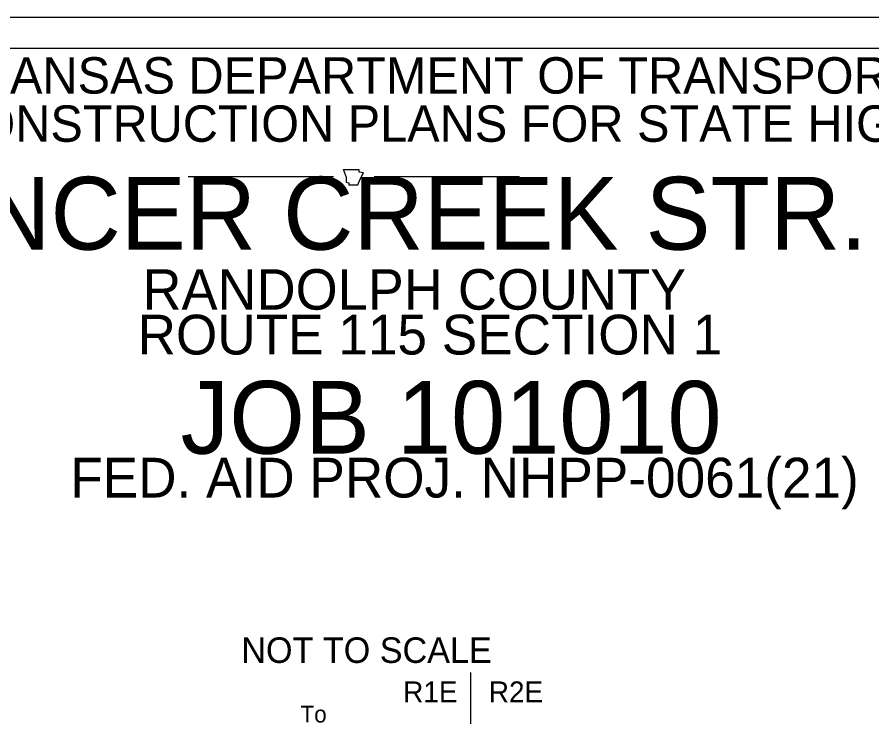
# Model space of a CAD drawing. Extents: x 1369885 to 1370219, y 379980 to 380218.
# Drawn here: x 1370011.5 to 1370119.1, y 380128.7 to 380217.9 of the extents above; entities that cross this region are included whole.
import ezdxf

# ---------------------------------------------------------------- set-up
doc = ezdxf.new("R2010")
doc.units = 0
for name, color, linetype in [('Default', 7, 'Continuous'), ('Level 2', 7, 'Continuous'), ('Level 24', 7, 'Continuous'), ('R_Draft', 7, 'Continuous'), ('R_No Plot', 7, 'Continuous'), ('STAMP_PE_FOSTER-SIGNATURE', 7, 'Continuous')]:
    doc.layers.add(name, color=color, linetype=linetype)

msp = doc.modelspace()

# ---------------------------------------------------------------- linework, layer by layer
at = {"layer": 'Default'}
for p, q in [((1370033.03, 380197.86), (1370051.34, 380197.86)), ((1370056.43, 380197.86), (1370074.74, 380197.86))]:
    msp.add_line(p, q, dxfattribs=at)
msp.add_lwpolyline([(1370052.53, 380198.79), (1370052.92, 380197.78), (1370052.92, 380197.15), (1370053.24, 380197.08), (1370053.24, 380196.84), (1370054.39, 380196.84), (1370054.63, 380197.47), (1370055.1, 380198.32), (1370054.55, 380198.4), (1370054.55, 380198.71), (1370052.61, 380198.71)], dxfattribs=at)
at = {"layer": 'R_Draft'}
msp.add_line((1370068.6, 380129.05), (1370068.6, 380135.48), dxfattribs=at)
at = {"layer": 'R_No Plot'}
msp.add_line((1369885.41, 380217.92), (1370218.74, 380217.92), dxfattribs=at)
msp.add_lwpolyline([(1369885.4, 380217.92), (1370218.74, 380217.92), (1370218.74, 380004.58), (1369885.4, 380004.58)], close=True, dxfattribs=at)
at = {"layer": 'STAMP_PE_FOSTER-SIGNATURE'}
for p, q in [((1369897.81, 380214.03), (1370213.99, 380214.03)), ((1370050.33, 380213.77), (1370050.33, 380213.77)), ((1370050.33, 380213.77), (1370050.33, 380213.77)), ((1370051.38, 380213.32), (1370051.38, 380213.32)), ((1370051.38, 380213.32), (1370051.38, 380213.32))]:
    msp.add_line(p, q, dxfattribs=at)

# ---------------------------------------------------------------- texts
at = {"layer": 'Default'}
for s, p in [(' R1E', (1370059.12, 380131.74)), ('R2E', (1370070.87, 380131.74))]:
    msp.add_text(s, height=2.63, dxfattribs=at).set_placement(p)
at = {"layer": 'Level 2'}
for s, height, p in [('ARKANSAS DEPARTMENT OF TRANSPORTATION', 4.5784, (1369998.04, 380208.3)), ('CONSTRUCTION PLANS FOR STATE HIGHWAY', 4.5784, (1370002.1, 380202.24)), ('SPENCER CREEK STR. & APPRS. (S)', 9.16, (1369982.37, 380188.67)), ('RANDOLPH COUNTY', 5.087, (1370027.29, 380181.13)), ('ROUTE 115 SECTION 1', 5, (1370026.68, 380175.49)), ('JOB 101010', 9.157, (1370032.09, 380163.01)), ('FED. AID PROJ. NHPP-0061(21)', 5, (1370018.21, 380157.5)), ('NOT TO SCALE', 3.2129, (1370039.73, 380136.7))]:
    msp.add_text(s, height=height, dxfattribs=at).set_placement(p)
at = {"layer": 'Level 24'}
msp.add_text('To', height=2.1, dxfattribs=at).set_placement((1370047.19, 380129.21))

doc.saveas('drawing.dxf')
